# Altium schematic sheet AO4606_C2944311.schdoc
size 127 x 101 mm
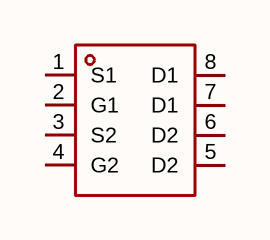
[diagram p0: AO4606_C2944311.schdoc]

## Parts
Q?  ao4606  [SOP-8_L4.9-W3.9-P1.27-LS6.0-BL]  (value not drawn)

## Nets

Not connected (* = marked no-connect by the designer): Q? 1(S1) 2(G1) 3(S2) 4(G2) 5(D2) 6(D2) 7(D1) 8(D1)

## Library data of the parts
Q? = ao4606: 数量:1个N沟道+1个P沟道;漏源电压(Vdss):30V;连续漏极电流(Id):6A；7.6A;导通电阻(RDS(on)):19mΩ@10V；24mΩ@10V;耗散功率(Pd):2W;阈值电压(Vgs(th)):1.7V；1.6V;; Manufacturer: UMW(友台半导体); Symbol: AO4606_C2944311; AddInBom: yes; ModelId: 75c24a7891ee4dd6bdac16a7163ff87e; ModelName: SOP-8_L4.9-W3.9-P1.27-LS6.0-BL-1; ModelTransform: 192.913,236.22,0,0,0,0,-0.393,2.749,0; Drain to Source Voltage: 30V; Pd - Power Dissipation: 2W; Gate Charge(Qg): 7.2nC@4.5V；9.8nC@4.5V; Input Capacitance(Ciss): 572pF；930pF; Reverse Transfer Capacitance (Crss@Vds): 65pF；115pF; Type: N沟道+P沟道; Output Capacitance(Coss): 81pF；148pF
